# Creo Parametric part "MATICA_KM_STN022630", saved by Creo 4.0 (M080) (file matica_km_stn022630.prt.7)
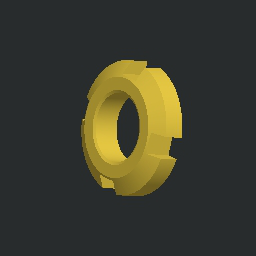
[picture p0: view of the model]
Units: millimeter Newton Second (mmNs); MM, TONNE, SECS
Materials in the file: OCEL_N

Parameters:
  NAZOV = "MATICA_KM_STN022630"
  NORMA = "STN 02 2630"
  PTC_MATERIAL_NAME = "OCEL_N"
  PLACEMENT = "B"

Other parameters: HMOTNOST, HUSTOTA, THREADS_PER_INCH

Created from: MATICA_KM_STN_022630.PRT

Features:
  1. datum plane "DTM1"
  2. pattern
  3. datum plane "DTM2"
  4. cut
  5. cut
  6. cut
  7. cut
  8. cut
  9. cut

Layers: ALL_AXIS, ALL_DATUM_PLANES, ALL_THREAD, DRAWING_NOTES

Family table entries: GENERIC, MATICA_KM0_STN_022630, MATICA_KM_STN022630, value(d_val), 2/+, 2/$, value(i_val), !End Line, MATICA_KM1_STN_022630, MATICA_KM_STN022630, MATICA_KM2_STN_022630, MATICA_KM_STN022630, MATICA_KM3_STN_022630, MATICA_KM_STN022630, MATICA_KM4_STN_022630, MATICA_KM_STN022630, MATICA_KM5_STN_022630, MATICA_KM_STN022630, !/C, 2/@, 2/9, MATICA_KM6_STN_022630, MATICA_KM_STN022630, d15, d14, d21, d22

Surfaces: 14 plane, 6 cone, 3 cylinder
